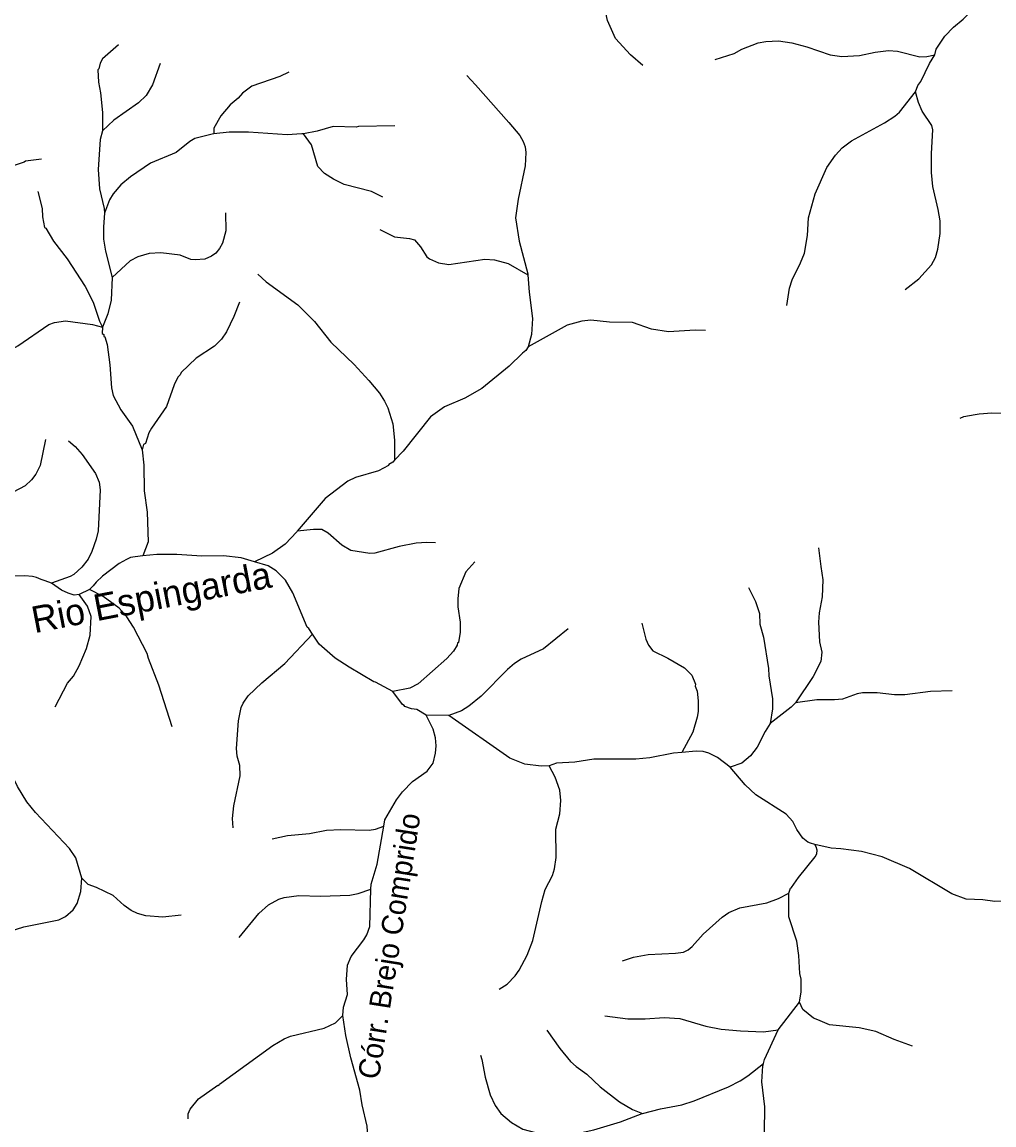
# Model space of a CAD drawing. Extents: x 280.4 to 335.6, y 8893.9 to 8949.5.
# Drawn here: x 296.28 to 303.6, y 8929.19 to 8937.49 of the extents above; entities that cross this region are included whole.
import ezdxf
from ezdxf.enums import TextEntityAlignment as Align

# ---------------------------------------------------------------- set-up
doc = ezdxf.new("R2010")
doc.units = 0
doc.header["$LTSCALE"] = 0.064
doc.layers.add('61', color=7, linetype='Continuous')
doc.layers.add('7', color=7, linetype='Continuous', lineweight=25)

msp = doc.modelspace()

# ---------------------------------------------------------------- linework, layer by layer
at = {"layer": '7'}
for p, q in [((296.7902, 8933.2155), (296.7126, 8933.1787)), ((299.0718, 8932.4476), (298.943, 8932.5196)), ((299.4938, 8932.268), (299.3249, 8932.2692)), ((301.9726, 8929.9007), (302.1325, 8930.1099))]:
    msp.add_line(p, q, dxfattribs=at)
for points in [[(300.9528, 8937.1606), (300.8623, 8937.2395), (300.7493, 8937.3616), (300.6893, 8937.498), (300.6527, 8937.6639), (300.6078, 8937.7967), (300.5979, 8937.8815), (300.6043, 8937.9472), (300.6305, 8938.0229), (300.6693, 8938.0802), (300.7227, 8938.1265), (300.8047, 8938.1819), (300.9916, 8938.2882), (301.0316, 8938.3166), (301.1436, 8938.4172), (301.1899, 8938.4701), (301.2253, 8938.5285), (301.2615, 8938.6421), (301.2807, 8938.8436), (301.2997, 8938.93), (301.2994, 8938.9761), (301.289, 8939.0021)], [(303.1512, 8937.2395), (303.1605, 8937.2815), (303.2274, 8937.3805), (303.2926, 8937.449), (303.3651, 8937.5087), (303.4195, 8937.5647), (303.5375, 8937.6606), (303.6463, 8937.7623), (303.7125, 8937.8119)], [(301.4978, 8937.2054), (301.6403, 8937.2498), (301.6993, 8937.2823), (301.822, 8937.3293), (301.8795, 8937.3404), (301.9741, 8937.345), (302.0745, 8937.3305), (302.1868, 8937.3005), (302.3642, 8937.2386), (302.4514, 8937.227), (302.585, 8937.2347), (302.7022, 8937.2606), (302.8016, 8937.2716), (302.871, 8937.2682), (303.0383, 8937.2253), (303.0896, 8937.2266), (303.1512, 8937.2395)], [(297.0076, 8937.3145), (296.8896, 8937.2097), (296.8718, 8937.1779), (296.8617, 8937.1342), (296.8543, 8937.1278), (296.8589, 8937.0333), (296.8733, 8936.9529), (296.8874, 8936.8068), (296.8896, 8936.6678)], [(303.0055, 8936.9624), (303.0235, 8937.01), (303.0462, 8937.0395), (303.1119, 8937.174), (303.1512, 8937.2395)], [(297.3223, 8937.1734), (297.2636, 8937.0147), (297.2177, 8936.9333), (297.1605, 8936.8797), (296.9744, 8936.7475), (296.8896, 8936.6678)], [(298.2904, 8937.1094), (298.2221, 8937.0757), (298.0131, 8937.0034), (297.9407, 8936.9524), (297.9084, 8936.9141), (297.8492, 8936.8643), (297.7783, 8936.7801), (297.7272, 8936.6878), (297.7253, 8936.6458)], [(299.6305, 8937.0845), (299.6941, 8937.0135), (299.9465, 8936.7315), (300.0276, 8936.6323), (300.054, 8936.5887), (300.0695, 8936.5484), (300.0733, 8936.505), (300.0675, 8936.4048), (300.0156, 8936.1536), (299.995, 8936.0137), (300.0235, 8935.8378), (300.0888, 8935.5918), (300.0893, 8935.584)], [(302.0372, 8935.3545), (302.0582, 8935.4827), (302.0767, 8935.5477), (302.141, 8935.674), (302.1704, 8935.7467), (302.1922, 8935.8793), (302.2004, 8936.0136), (302.2517, 8936.1927), (302.3372, 8936.3922), (302.4033, 8936.485), (302.4547, 8936.539), (302.5239, 8936.5927), (302.773, 8936.7273), (302.8505, 8936.7787), (302.8847, 8936.8094), (303.0055, 8936.9624)], [(302.928, 8935.4735), (303.0314, 8935.5551), (303.1268, 8935.6594), (303.1555, 8935.715), (303.1739, 8935.7781), (303.1902, 8935.8953), (303.1902, 8935.9899), (303.1771, 8936.0754), (303.1361, 8936.2479), (303.1264, 8936.3535), (303.1263, 8936.4967), (303.1353, 8936.6748), (303.1282, 8936.7089), (303.0546, 8936.8154), (303.0273, 8936.8823), (303.0055, 8936.9624)], [(296.8896, 8936.6678), (296.8717, 8936.6015), (296.8556, 8936.3768), (296.8668, 8936.2305), (296.9003, 8936.0843), (296.9034, 8936.0472)], [(298.3998, 8936.6464), (298.3872, 8936.6443), (298.279, 8936.6371), (297.9862, 8936.6574), (297.8422, 8936.6574), (297.7253, 8936.6458)], [(299.0876, 8936.706), (298.8153, 8936.7006), (298.798, 8936.696), (298.6234, 8936.7006), (298.5048, 8936.6643), (298.3998, 8936.6464)], [(297.7253, 8936.6458), (297.7227, 8936.6455), (297.5826, 8936.609), (297.5457, 8936.5874), (297.4424, 8936.5041), (297.2506, 8936.4239), (297.0985, 8936.3212), (297.0261, 8936.2603), (296.9685, 8936.1935), (296.942, 8936.1473), (296.9034, 8936.0472)], [(298.9981, 8936.1687), (298.9118, 8936.2123), (298.7058, 8936.2643), (298.6265, 8936.3039), (298.5594, 8936.3468), (298.5075, 8936.3991), (298.4616, 8936.5615), (298.3998, 8936.6464)], [(296.4306, 8936.4536), (296.3083, 8936.4394), (296.2994, 8936.4315), (296.1939, 8936.3976), (295.9927, 8936.2902), (295.9312, 8936.264), (295.7434, 8936.1551), (295.6908, 8936.1342), (295.6258, 8936.1224)], [(296.4018, 8936.2114), (296.4334, 8936.0828), (296.4366, 8936.0213), (296.4527, 8935.9402), (296.461, 8935.9363), (296.5187, 8935.8368), (296.6225, 8935.7053), (296.7571, 8935.4963), (296.8187, 8935.3796), (296.8653, 8935.2357), (296.8875, 8935.1892)], [(296.9034, 8936.0472), (296.8957, 8935.9441), (296.8972, 8935.853), (296.9102, 8935.7627), (296.9622, 8935.5642)], [(297.8131, 8936.0511), (297.8166, 8935.9145), (297.7916, 8935.8224), (297.7694, 8935.7814), (297.7415, 8935.7475), (297.7085, 8935.7238), (297.6593, 8935.7027), (297.5857, 8935.6964), (297.5533, 8935.7007), (297.4719, 8935.7311), (297.3273, 8935.7506), (297.2394, 8935.7455), (297.1546, 8935.7202), (297.0977, 8935.6886), (296.9622, 8935.5642)], [(298.9744, 8935.9265), (299.0859, 8935.8693), (299.1984, 8935.8578), (299.2367, 8935.8464), (299.2816, 8935.7954), (299.3288, 8935.7197), (299.3478, 8935.7041), (299.4159, 8935.6756), (299.4939, 8935.6613), (299.7644, 8935.7026), (299.8388, 8935.6961), (299.9419, 8935.6685), (300.0893, 8935.584)], [(298.057, 8935.5886), (298.12, 8935.532), (298.3581, 8935.358), (298.4835, 8935.2341), (298.6064, 8935.0763), (298.7816, 8934.9089), (298.8935, 8934.7889), (298.9725, 8934.6926), (299.0113, 8934.6344), (299.0341, 8934.5832), (299.0733, 8934.4632), (299.0849, 8934.3401), (299.0848, 8934.1885)], [(300.0893, 8935.584), (300.0975, 8935.4537), (300.1227, 8935.2565), (300.1153, 8935.1362), (300.0905, 8935.0416)], [(296.9622, 8935.5642), (296.953, 8935.3925), (296.928, 8935.2915), (296.8875, 8935.1892)], [(297.918, 8935.3796), (297.8769, 8935.2698), (297.8216, 8935.1563), (297.7835, 8935.0998), (297.7311, 8935.0468), (297.5922, 8934.957), (297.4803, 8934.8481), (297.4722, 8934.8306), (297.455, 8934.8144), (297.4275, 8934.7555), (297.3692, 8934.5935), (297.2561, 8934.4296), (297.2379, 8934.3945), (297.211, 8934.3143), (297.1978, 8934.3062), (297.1876, 8934.2665)], [(296.0514, 8934.9502), (296.1873, 8935.0129), (296.252, 8935.05), (296.4839, 8935.2091), (296.5281, 8935.2263), (296.6088, 8935.2389), (296.8123, 8935.2101), (296.8875, 8935.1892)], [(296.8875, 8935.1892), (296.8864, 8935.1438), (296.8982, 8935.1347), (296.8976, 8935.1194), (296.905, 8935.1166), (296.9243, 8935.0602), (296.9435, 8934.9062), (296.9563, 8934.7336), (296.9689, 8934.6767), (297.0275, 8934.5671), (297.1146, 8934.4456), (297.1876, 8934.2665)], [(301.4242, 8935.1649), (301.3485, 8935.1669), (301.1468, 8935.1561), (301.02, 8935.1754), (300.8769, 8935.2245), (300.7025, 8935.2277), (300.5618, 8935.2421), (300.4955, 8935.2362), (300.3845, 8935.205), (300.0905, 8935.0416)], [(300.0905, 8935.0416), (300.0733, 8935.0141), (300.0473, 8934.9954), (299.9485, 8934.8967), (299.7428, 8934.7292), (299.6139, 8934.6565), (299.4608, 8934.5896), (299.3552, 8934.516), (299.1504, 8934.2569), (299.0848, 8934.1885)], [(303.3404, 8934.5053), (303.3687, 8934.5177), (303.4547, 8934.5319), (303.4851, 8934.5369), (303.579, 8934.5447), (303.7499, 8934.5401), (303.8427, 8934.5544), (304.0475, 8934.564), (304.1444, 8934.5485), (304.317, 8934.4907), (304.3913, 8934.4762), (304.4504, 8934.4745), (304.5962, 8934.5092), (304.6762, 8934.5379), (304.7033, 8934.5549)], [(296.4598, 8934.3445), (296.4197, 8934.149), (296.3872, 8934.0849), (296.3542, 8934.0407), (296.3059, 8933.996), (296.2154, 8933.949), (296.1727, 8933.9066), (296.1427, 8933.8396), (296.1078, 8933.7882), (296.0387, 8933.7248), (295.982, 8933.6521), (295.9245, 8933.607), (295.8608, 8933.578), (295.8236, 8933.5507), (295.8215, 8933.5397), (295.7539, 8933.442), (295.6877, 8933.4038)], [(296.6318, 8934.3348), (296.6817, 8934.2916), (296.736, 8934.2307), (296.8359, 8934.088), (296.8632, 8934.0241), (296.8715, 8933.9659), (296.8556, 8933.6571), (296.8412, 8933.5955), (296.8075, 8933.5021), (296.7794, 8933.4441), (296.7323, 8933.3838), (296.6718, 8933.3285), (296.6449, 8933.314), (296.5043, 8933.2645)], [(297.1876, 8934.2665), (297.1993, 8934.1514), (297.2026, 8933.9588), (297.2234, 8933.7979), (297.2311, 8933.5749), (297.1918, 8933.4704)], [(299.0848, 8934.1885), (299.0719, 8934.175), (299.0421, 8934.1572), (299.0395, 8934.1483), (298.9649, 8934.1083), (298.7929, 8934.0589), (298.7353, 8934.0301), (298.563, 8933.8998), (298.3542, 8933.6546)], [(299.3946, 8933.5664), (299.3283, 8933.5707), (299.2475, 8933.564), (299.1216, 8933.5404), (298.9379, 8933.4882), (298.9009, 8933.4862), (298.7576, 8933.5099), (298.6892, 8933.5505), (298.5865, 8933.6391), (298.5393, 8933.6682), (298.4755, 8933.6684), (298.3542, 8933.6546)], [(298.3542, 8933.6546), (298.3503, 8933.65), (298.2639, 8933.5578), (298.1679, 8933.489), (298.0317, 8933.4246)], [(302.2745, 8933.5297), (302.2937, 8933.3889), (302.3074, 8933.2885), (302.3042, 8933.1598), (302.2804, 8933.0391), (302.2755, 8932.9696), (302.2834, 8932.8216), (302.301, 8932.7432), (302.2941, 8932.675), (302.235, 8932.5611), (302.1014, 8932.362)], [(297.1918, 8933.4704), (297.133, 8933.4626), (297.0989, 8933.4558), (297.0692, 8933.4421), (297.0139, 8933.4109), (296.8872, 8933.3161), (296.8403, 8933.2701), (296.8175, 8933.244), (296.7902, 8933.2155)], [(298.0317, 8933.4246), (297.9325, 8933.4532), (297.7992, 8933.47), (297.6359, 8933.467), (297.4473, 8933.4781), (297.296, 8933.4782), (297.1918, 8933.4704)], [(298.4693, 8932.879), (298.4417, 8932.9213), (298.4274, 8932.9322), (298.3195, 8933.1903), (298.2644, 8933.2862), (298.1963, 8933.3576), (298.1348, 8933.3948), (298.0317, 8933.4246)], [(299.6893, 8933.4246), (299.6223, 8933.3485), (299.5699, 8933.2241), (299.5615, 8933.1456), (299.5632, 8933.0863), (299.579, 8932.9704), (299.579, 8932.8945), (299.5662, 8932.8174), (299.5601, 8932.8136), (299.5573, 8932.7971), (299.5283, 8932.7526), (299.4804, 8932.6966), (299.2629, 8932.505), (299.2002, 8932.4733), (299.0718, 8932.4476)], [(296.5043, 8933.2645), (296.4564, 8933.2815), (296.4269, 8933.2924), (296.3927, 8933.3066), (296.3621, 8933.3132), (296.3031, 8933.3182), (296.0719, 8933.3103), (295.8568, 8933.3311), (295.8413, 8933.3369)], [(296.7126, 8933.1787), (296.674, 8933.1745), (296.6293, 8933.1873), (296.5795, 8933.2121), (296.5043, 8933.2645)], [(296.5318, 8932.333), (296.625, 8932.5099), (296.6695, 8932.5628), (296.7132, 8932.6416), (296.767, 8932.7715), (296.7961, 8932.8714), (296.8025, 8933.0125), (296.7746, 8933.0913), (296.7126, 8933.1787)], [(297.4128, 8932.1835), (297.3134, 8932.4964), (297.2343, 8932.6967), (297.2248, 8932.7344), (297.1226, 8932.9327), (297.0724, 8933.0098), (297.014, 8933.0747), (296.893, 8933.1642), (296.7902, 8933.2155)], [(301.7489, 8933.2302), (301.8025, 8933.1265), (301.8317, 8933.0342), (301.8345, 8932.9543), (301.8627, 8932.856), (301.8997, 8932.6218), (301.9013, 8932.5656), (301.9299, 8932.3922), (301.9285, 8932.3178), (301.912, 8932.207)], [(300.3912, 8932.9205), (300.2053, 8932.7693), (300.0397, 8932.6913), (299.9885, 8932.6597), (299.9346, 8932.6147), (299.7364, 8932.4137), (299.6456, 8932.339), (299.5892, 8932.303), (299.4938, 8932.268)], [(300.9476, 8932.9629), (300.9777, 8932.841), (300.9966, 8932.7968), (301.0285, 8932.7555), (301.1431, 8932.6992), (301.2663, 8932.6273), (301.3237, 8932.5713), (301.351, 8932.5029), (301.3484, 8932.4875), (301.3623, 8932.45), (301.3702, 8932.3769), (301.3702, 8932.2969), (301.3636, 8932.2541), (301.3304, 8932.1434), (301.2474, 8931.9897)], [(297.8708, 8931.422), (297.8664, 8931.4934), (297.8773, 8931.5881), (297.9254, 8931.814), (297.9222, 8931.8925), (297.9014, 8931.9611), (297.8966, 8932.0188), (297.9127, 8932.2284), (297.9319, 8932.3266), (297.9463, 8932.3602), (297.9835, 8932.4151), (298.0885, 8932.5137), (298.2602, 8932.6585), (298.4693, 8932.879)], [(298.943, 8932.5196), (298.9312, 8932.5212), (298.7433, 8932.6302), (298.6389, 8932.6987), (298.5183, 8932.8038), (298.4693, 8932.879)], [(299.3249, 8932.2692), (299.2544, 8932.3129), (299.2137, 8932.3173), (299.163, 8932.3342), (299.1589, 8932.3434), (299.1445, 8932.3492), (299.0718, 8932.4476)], [(303.2803, 8932.4545), (303.1173, 8932.4483), (302.9247, 8932.4243), (302.8479, 8932.4243), (302.7168, 8932.4386), (302.6055, 8932.4371), (302.5678, 8932.4309), (302.4566, 8932.3895), (302.3969, 8932.3843), (302.2626, 8932.3858), (302.1014, 8932.362)], [(302.1014, 8932.362), (302.0701, 8932.3311), (301.912, 8932.207)], [(299.0051, 8931.4351), (299.0131, 8931.4818), (299.0994, 8931.6341), (299.1445, 8931.6941), (299.2208, 8931.7717), (299.3306, 8931.8496), (299.3775, 8931.9083), (299.3935, 8931.9836), (299.3982, 8932.0397), (299.3936, 8932.1004), (299.3761, 8932.1644), (299.3249, 8932.2692)], [(300.2502, 8931.8885), (300.1889, 8931.8857), (300.0657, 8931.9021), (299.9543, 8931.9465), (299.4938, 8932.268)], [(301.912, 8932.207), (301.8731, 8932.1471), (301.8136, 8932.0283), (301.7647, 8931.9647), (301.6981, 8931.9078), (301.6106, 8931.8794)], [(301.2474, 8931.9897), (301.1858, 8931.9845), (301.0073, 8931.9495), (300.9008, 8931.9381), (300.5851, 8931.9398), (300.4426, 8931.9156), (300.3036, 8931.9094), (300.2502, 8931.8885)], [(301.6106, 8931.8794), (301.5151, 8931.9512), (301.4501, 8931.9838), (301.4079, 8931.9957), (301.3549, 8931.9989), (301.2474, 8931.9897)], [(296.7338, 8931.0423), (296.6872, 8931.1966), (296.6407, 8931.2669), (296.3848, 8931.5388), (296.3194, 8931.6175), (296.2486, 8931.7327), (296.1883, 8931.8562), (296.1631, 8931.8865)], [(299.8741, 8930.2069), (299.932, 8930.2458), (299.9937, 8930.3089), (300.0236, 8930.3515), (300.0847, 8930.4642), (300.1275, 8930.5754), (300.1928, 8930.8683), (300.2183, 8930.9579), (300.2744, 8931.0642), (300.2893, 8931.1135), (300.3018, 8931.1985), (300.3001, 8931.411), (300.3289, 8931.528), (300.3371, 8931.627), (300.3284, 8931.7068), (300.2955, 8931.8037), (300.2502, 8931.8885)], [(302.2492, 8931.2979), (302.2153, 8931.3059), (302.1955, 8931.3136), (302.1567, 8931.3437), (302.1128, 8931.4096), (302.0826, 8931.4692), (302.0336, 8931.5257), (301.8047, 8931.6715), (301.725, 8931.7449), (301.6106, 8931.8794)], [(298.1642, 8931.3399), (298.2804, 8931.3638), (298.4462, 8931.38), (298.5747, 8931.4038), (298.681, 8931.4103), (298.8944, 8931.4048), (298.9433, 8931.4122), (299.0051, 8931.4351)], [(298.9081, 8930.9617), (298.9091, 8930.9993), (298.9559, 8931.1478), (299.0051, 8931.4351)], [(302.0513, 8930.9317), (302.064, 8930.9677), (302.0734, 8930.9722), (302.1262, 8931.0482), (302.2509, 8931.2049), (302.2624, 8931.2271), (302.2658, 8931.2538), (302.2591, 8931.2796), (302.2492, 8931.2979)], [(303.669, 8930.8708), (303.6019, 8930.8677), (303.5116, 8930.8792), (303.3865, 8930.8842), (303.2791, 8930.9261), (302.9606, 8931.1173), (302.7559, 8931.2037), (302.5981, 8931.2434), (302.4431, 8931.2632), (302.3706, 8931.2682), (302.2492, 8931.2979)], [(295.8669, 8929.9014), (295.8778, 8930.0075), (295.8737, 8930.0556), (295.8936, 8930.1412), (295.9182, 8930.2064), (295.9536, 8930.3004), (295.9803, 8930.3482), (295.9795, 8930.3655), (295.9869, 8930.371), (295.9936, 8930.4052), (296.0362, 8930.5165), (296.0608, 8930.5546), (296.1209, 8930.607), (296.1861, 8930.6428), (296.2974, 8930.6762), (296.5596, 8930.7291), (296.6103, 8930.7558), (296.6688, 8930.8063), (296.699, 8930.8528), (296.7258, 8930.9427), (296.7338, 8931.0423)], [(297.4814, 8930.7642), (297.3427, 8930.7498), (297.2147, 8930.7595), (297.1527, 8930.7765), (297.1047, 8930.8003), (297.0519, 8930.8385), (296.969, 8930.9129), (296.8438, 8930.9731), (296.7809, 8930.9967), (296.7338, 8931.0423)], [(297.9162, 8930.5963), (298.0636, 8930.7773), (298.138, 8930.8432), (298.2147, 8930.8862), (298.255, 8930.8991), (298.3662, 8930.9129), (298.5275, 8930.9082), (298.7499, 8930.9161), (298.813, 8930.9285), (298.9081, 8930.9617)], [(298.6965, 8930.0094), (298.6964, 8930.0103), (298.7009, 8930.0726), (298.7314, 8930.1668), (298.7251, 8930.2805), (298.7316, 8930.3882), (298.76, 8930.4532), (298.855, 8930.5793), (298.8772, 8930.6177), (298.9005, 8930.6792), (298.9081, 8930.9617)], [(300.8012, 8930.4221), (300.8829, 8930.4496), (300.9935, 8930.4683), (301.2001, 8930.478), (301.2605, 8930.4874), (301.2954, 8930.5045), (301.3254, 8930.5291), (301.4089, 8930.6218), (301.5504, 8930.7508), (301.6006, 8930.7849), (301.6837, 8930.82), (301.8879, 8930.8578), (301.9746, 8930.8896), (302.0513, 8930.9317)], [(302.1325, 8930.1099), (302.1451, 8930.1887), (302.1451, 8930.283), (302.1343, 8930.3257), (302.1285, 8930.4618), (302.1123, 8930.569), (302.0513, 8930.7512), (302.0513, 8930.9317)], [(302.9817, 8929.7794), (302.8457, 8929.8285), (302.7078, 8929.89), (302.5824, 8929.9166), (302.3593, 8929.9389), (302.2718, 8929.9765), (302.2387, 8929.9908), (302.1573, 8930.0559), (302.1325, 8930.1099)], [(297.5329, 8929.2313), (297.5331, 8929.2705), (297.5468, 8929.306), (297.6115, 8929.3834), (297.7565, 8929.4853), (297.7641, 8929.484), (297.7688, 8929.4939), (298.1712, 8929.7845), (298.2558, 8929.8331), (298.3042, 8929.8531), (298.5555, 8929.9134), (298.6409, 8929.9539), (298.6965, 8930.0094)], [(298.2945, 8927.823), (298.3192, 8927.8695), (298.3269, 8927.9054), (298.333, 8928.0138), (298.3349, 8928.0482), (298.3557, 8928.1187), (298.3869, 8928.1596), (298.4584, 8928.2313), (298.5903, 8928.392), (298.6223, 8928.4511), (298.6388, 8928.5188), (298.6818, 8928.6202), (298.7221, 8928.6694), (298.7438, 8928.6959), (298.851, 8928.7842), (298.8823, 8928.8599), (298.8913, 8928.9065), (298.8914, 8928.9962), (298.8786, 8929.1771), (298.8422, 8929.337), (298.8247, 8929.4475), (298.7573, 8929.6919), (298.72, 8929.8589), (298.6965, 8930.0094)], [(300.6692, 8930.0068), (300.84, 8929.9854), (300.9711, 8929.9838), (301.1143, 8929.9949), (301.2311, 8929.9865), (301.4267, 8929.9305), (301.5434, 8929.9075), (301.6894, 8929.8942), (301.8628, 8929.8878), (301.9726, 8929.9007)], [(300.2312, 8929.8988), (300.3282, 8929.7605), (300.4085, 8929.6631), (300.4512, 8929.6251), (300.5327, 8929.5691), (300.6325, 8929.474), (300.779, 8929.3613), (300.8759, 8929.3018), (300.9508, 8929.2718)], [(301.8606, 8929.6483), (301.8685, 8929.6795), (301.9726, 8929.9007)], [(299.7324, 8929.7112), (299.7437, 8929.679), (299.7679, 8929.5449), (299.8057, 8929.4127), (299.8431, 8929.3328), (299.8856, 8929.2727), (299.9658, 8929.2041), (300.0506, 8929.1549), (300.205, 8929.1133), (300.3156, 8929.1043), (300.47, 8929.1231), (300.5858, 8929.1496), (300.7864, 8929.2102), (300.9491, 8929.2713), (300.9508, 8929.2718)], [(300.9508, 8929.2718), (301.088, 8929.3086), (301.248, 8929.3375), (301.3401, 8929.3664), (301.5974, 8929.4729), (301.6875, 8929.5185), (301.7438, 8929.5547), (301.8606, 8929.6483)], [(301.9102, 8928.8787), (301.885, 8928.9779), (301.8693, 8929.129), (301.8724, 8929.3216), (301.8501, 8929.5111), (301.8563, 8929.6312), (301.8606, 8929.6483)]]:
    msp.add_lwpolyline(points, dxfattribs=at)

# ---------------------------------------------------------------- texts
at = {"layer": '61'}
for s, height, rotation, p in [('Rio Espingarda', 0.2, 10.938, (297.2745, 8933.06)), ('Córr. Brejo Comprido', 0.16, 81.027, (299.1246, 8930.521))]:
    msp.add_text(s, height=height, rotation=rotation, dxfattribs=at).set_placement(p, align=Align.CENTER)

doc.saveas('drawing.dxf')
